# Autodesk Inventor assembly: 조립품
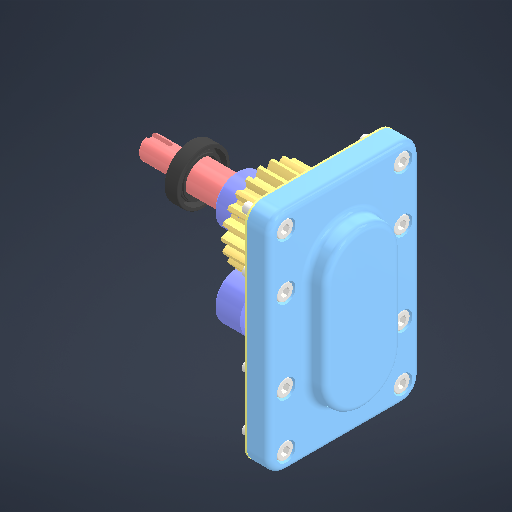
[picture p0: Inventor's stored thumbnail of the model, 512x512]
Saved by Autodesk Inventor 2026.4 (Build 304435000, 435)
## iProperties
Created: 2026-10
Part Number: 조립품
Document SubType Name: Assembly
Designer: user
Author: user
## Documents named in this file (11)
- C:\Users\user\Desktop\761003V1013\조립품.iam
- C:\Users\user\Desktop\761003V1013\부품.ipt
- C:\Users\user\Desktop\761003V1013\6각 구멍붙이 볼트 M5x16\6각 구멍붙이 볼트 M5x16.ipt
- C:\Users\user\Desktop\761003V1013\개스킷\개스킷.ipt
- C:\Users\user\Desktop\761003V1013\구동 축\구동 축.ipt
- C:\Users\user\Desktop\761003V1013\베어링 부시\베어링 부시.ipt
- C:\Users\user\Desktop\761003V1013\스퍼 기어\스퍼 기어.ipt
- C:\Users\user\Desktop\761003V1013\오일 실 16 28 7\오일 실 16 28 7.ipt
- C:\Users\user\Desktop\761003V1013\종동 축\종동 축.ipt
- C:\Users\user\Desktop\761003V1013\커버\커버.ipt
- C:\Users\user\Desktop\761003V1013\평행 키 6x6x18\평행 키 6x6x18.ipt
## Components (10 placed, 3 different names)
1. 6각 구멍붙이 볼트 M5x16:1
2. 개스킷:1 — 각도:4
3. 구동 축:1 — 각도:3
4. 6각 구멍붙이 볼트 M5x16:2
5. 6각 구멍붙이 볼트 M5x16:3
6. 6각 구멍붙이 볼트 M5x16:4
7. 6각 구멍붙이 볼트 M5x16:5
8. 6각 구멍붙이 볼트 M5x16:6
9. 6각 구멍붙이 볼트 M5x16:7
10. 6각 구멍붙이 볼트 M5x16:8
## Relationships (2: Angle 2)
- 각도:3 [Angle]: 구동 축:1
- 각도:4 [Angle]: 개스킷:1
